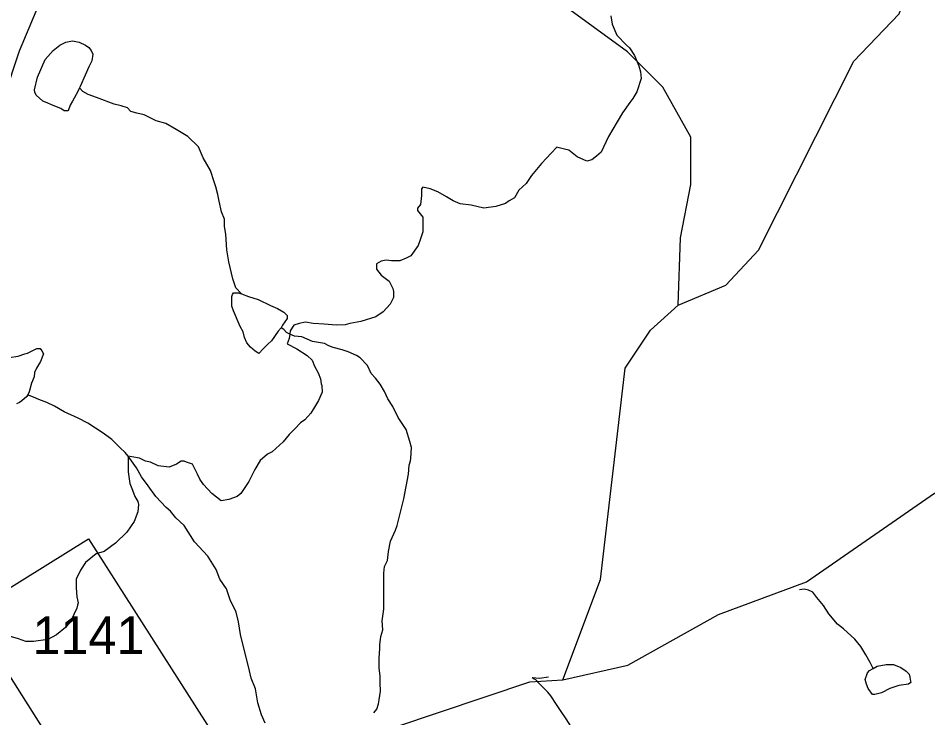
# Model space of a CAD drawing. Extents: x 2001466 to 2224147, y 644118 to 847247.
# Drawn here: x 2014651 to 2017667, y 716870 to 719190 of the extents above; entities that cross this region are included whole.
import ezdxf

# ---------------------------------------------------------------- set-up
doc = ezdxf.new("R2010")
doc.units = 0
for name, color, linetype in [('Exist Hydrographic Creek Single Shore', 7, 'Continuous'), ('Exist Hydrographic Misc Water Feature', 7, 'Continuous'), ('Exist Road Non-System Type 51', 7, 'Continuous'), ('Exist Road Secondary Type 51 Attributed', 7, 'Continuous'), ('Exist Road Secondary Type 51 Number Label', 7, 'Continuous')]:
    doc.layers.add(name, color=color, linetype=linetype)

msp = doc.modelspace()

# ---------------------------------------------------------------- linework, layer by layer
at = {"layer": 'Exist Hydrographic Creek Single Shore'}
for points in [[(2016457.2, 716996.2), (2016673.1, 717044.4), (2016973.1, 717212.1), (2017265.1, 717321), (2017690.1, 717614.3), (2018156, 717755.6), (2018439.2, 717930.3), (2018981.2, 718096.5)], [(2015574, 716610.6), (2015590, 716646.4), (2015749.1, 716787.6), (2016348.1, 716988.6), (2016457.2, 716996.2)]]:
    msp.add_lwpolyline(points, dxfattribs=at)
at = {"layer": 'Exist Hydrographic Misc Water Feature'}
for points in [[(2016672.1, 719078.7), (2016330.2, 719328.4), (2015864.2, 719554.5)], [(2016839.2, 718238.5), (2016997.1, 718304.3), (2017106.2, 718420.2), (2017422.1, 719047), (2017572.2, 719204.7), (2017614.1, 719321.9), (2017622.1, 719479.3), (2017588.2, 719502.9)], [(2016616.5, 719198), (2016620.6, 719170.1), (2016636.6, 719134.1), (2016668.6, 719100.1), (2016678.6, 719092.1), (2016694.6, 719066.2), (2016708.6, 719032.2), (2016714.7, 719012.2), (2016716.6, 718990.2), (2016702.6, 718946.2), (2016688.7, 718924.2), (2016678.8, 718910.2), (2016654.8, 718876.1), (2016636.8, 718846.2), (2016608.7, 718798.1), (2016584.7, 718746.1), (2016568.9, 718732.1), (2016552.9, 718720.1), (2016536.9, 718716.1), (2016504.9, 718730.1), (2016476.9, 718752), (2016462.9, 718756), (2016444.9, 718760), (2016436.9, 718762), (2016418.8, 718742.1), (2016402.8, 718726), (2016386.8, 718708), (2016352.8, 718668), (2016335, 718642), (2016311, 718620), (2016296.8, 718594), (2016279, 718584), (2016266.9, 718575.9), (2016235.1, 718565.9), (2016195.1, 718559.9), (2016153.1, 718569.9), (2016117, 718573.9), (2016093, 718583.9), (2016071.1, 718597.8), (2016043, 718613.8), (2016016.9, 718623.8), (2015992.9, 718629.8), (2015989, 718623.8), (2015989, 718601.8), (2015987, 718591.8), (2015984.9, 718571.8), (2015975.1, 718559.8), (2015975.1, 718551.8), (2015992.9, 718529.8), (2015992.9, 718511.8), (2015992.9, 718481.8), (2015984.9, 718457.8), (2015977.1, 718435.8), (2015953.2, 718401.8), (2015937.2, 718393.8), (2015917.1, 718385.8), (2015889.2, 718385.8), (2015871.1, 718387.7), (2015855.1, 718383.7), (2015839.1, 718375.7), (2015839.1, 718357.7), (2015855.1, 718337.7), (2015881.2, 718317.7), (2015893.1, 718293.8), (2015895.1, 718283.8), (2015895.1, 718263.8), (2015885.1, 718241.8), (2015861.3, 718215.7), (2015837.3, 718199.7), (2015787.3, 718183.7), (2015751.2, 718177.7), (2015735.2, 718173.6), (2015705.2, 718171.6), (2015665.3, 718175.6), (2015629.2, 718177.6), (2015603.3, 718181.6), (2015583.2, 718177.6), (2015565.2, 718171.6), (2015553.3, 718153.6), (2015551.3, 718141.6)], [(2014854.9, 718959.1), (2014848.9, 718947.1), (2014830.9, 718915), (2014822.9, 718901.1), (2014817, 718883), (2014803, 718883), (2014793, 718891), (2014761, 718903), (2014746.8, 718909), (2014732.9, 718915), (2014710.9, 718935), (2014706.8, 718945), (2014705, 718953), (2014714.8, 718994.9), (2014740.9, 719053), (2014766.9, 719083), (2014788.9, 719101), (2014809, 719111), (2014830.7, 719115), (2014852.8, 719111), (2014874.8, 719101), (2014884.8, 719093.1), (2014892.8, 719083.1), (2014899, 719071.1), (2014894.9, 719049.1), (2014884.8, 719029.1), (2014872.9, 719001.1), (2014856.9, 718963.1), (2014854.9, 718959.1)], [(2016839.2, 718238.5), (2016847.2, 718461.5), (2016881.2, 718638), (2016881.2, 718795.6), (2016789.1, 718961.4), (2016672.1, 719078.7)], [(2015391.3, 718275.5), (2015373.3, 718295.4), (2015363.2, 718325.5), (2015349.1, 718381.5), (2015343.1, 718421.4), (2015339.2, 718473.4), (2015335.1, 718499.4), (2015335.1, 718523.4), (2015325.1, 718547.4), (2015317.1, 718583.4), (2015313, 718605.4), (2015307, 718631.3), (2015301.1, 718647.4), (2015289, 718685.4), (2015265, 718727.3), (2015249, 718763.3), (2015213.1, 718797.4), (2015175, 718821.3), (2015140.9, 718841.2), (2015109, 718849.2), (2015069, 718869.2), (2015045, 718875.2), (2015024.9, 718881.1), (2015013, 718893.1), (2014992.9, 718899.2), (2014968.9, 718905.2), (2014910.9, 718927.1), (2014883, 718937.1), (2014864.9, 718947.1), (2014854.9, 718959.1)], [(2015523.2, 718163.6), (2015513.3, 718151.6), (2015491.4, 718119.5), (2015479.3, 718109.5), (2015463.3, 718093.5), (2015449.3, 718077.5), (2015437.4, 718085.5), (2015421.5, 718099.5), (2015409.4, 718113.5), (2015401.4, 718131.5), (2015397.3, 718149.5), (2015387.2, 718167.4), (2015365.3, 718219.5), (2015359.3, 718235.5), (2015359.3, 718251.5), (2015359.3, 718267.5), (2015361.2, 718273.5), (2015365.3, 718279.5), (2015381.3, 718279.5), (2015391.3, 718275.5)], [(2015391.3, 718275.5), (2015415.3, 718267.5), (2015447.3, 718257.5), (2015487.3, 718237.5), (2015511.3, 718227.5), (2015531.4, 718215.5), (2015537.3, 718209.5), (2015543.3, 718203.5), (2015543.3, 718193.6), (2015527.3, 718171.5), (2015523.2, 718163.6)], [(2016457.2, 716996.2), (2016582, 717328.4), (2016664.1, 718028.9), (2016748.1, 718155.1), (2016839.2, 718238.5)], [(2015551.3, 718141.6), (2015541.2, 718147.6), (2015531.4, 718157.6), (2015523.2, 718163.6)], [(2015551.3, 718141.6), (2015549.2, 718127.6), (2015543.5, 718109.6), (2015575.2, 718093.6), (2015609.3, 718071.6), (2015625.5, 718055.6), (2015633.5, 718035.6), (2015645.4, 718013.7), (2015653.4, 717993.7), (2015655.4, 717977.7), (2015657.5, 717971.7), (2015659.3, 717949.7), (2015647.4, 717921.6), (2015637.4, 717905.6), (2015621.6, 717879.7), (2015601.5, 717857.7), (2015587.5, 717847.7), (2015569.5, 717829.7), (2015549.4, 717809.6), (2015529.5, 717785.6), (2015493.4, 717751.6), (2015477.4, 717743.6), (2015453.4, 717723.6), (2015435.4, 717693.6), (2015415.7, 717653.5), (2015389.7, 717613.5), (2015377.6, 717603.6), (2015349.7, 717593.5), (2015323.6, 717589.5), (2015293.7, 717613.4), (2015265.6, 717643.5), (2015253.7, 717661.5), (2015245.7, 717677.5), (2015235.7, 717697.5), (2015229.5, 717711.5), (2015209.6, 717717.4), (2015201.6, 717721.4), (2015191.6, 717721.4), (2015175.6, 717711.4), (2015151.6, 717701.4), (2015115.7, 717705.4), (2015089.7, 717717.4), (2015073.7, 717721.4), (2015053.6, 717731.4), (2015027.5, 717735.3), (2015016, 717737.3)], [(2015829.9, 716885.9), (2015840, 716897.9), (2015845.9, 716915.9), (2015848, 716929.9), (2015852.1, 716957.9), (2015851.9, 716985.9), (2015851.9, 717007.9), (2015847.8, 717035.9), (2015847.8, 717067.9), (2015849.8, 717099.8), (2015849.8, 717111.8), (2015853.9, 717139.9), (2015859.9, 717161.9), (2015857.8, 717191.9), (2015863.8, 717229.8), (2015863.8, 717271.8), (2015863.8, 717321.9), (2015863.8, 717349.9), (2015865.8, 717371.8), (2015875.6, 717391.8), (2015879.5, 717421.8), (2015885.7, 717455.9), (2015901.7, 717491.8), (2015907.6, 717507.8), (2015929.6, 717595.9), (2015945.6, 717677.8), (2015947.4, 717707.9), (2015951.5, 717721.9), (2015953.6, 717729.9), (2015955.4, 717765.9), (2015949.5, 717785.8), (2015937.4, 717825.8), (2015911.3, 717865.9), (2015893.3, 717901.8), (2015877.3, 717927.8), (2015865.4, 717951.8), (2015851.4, 717975.8), (2015835.5, 717995.8), (2015821.3, 718011.7), (2015809.4, 718037.7), (2015785.4, 718063.7), (2015773.3, 718071.7), (2015745.2, 718083.7), (2015725.3, 718089.7), (2015695.2, 718097.7), (2015681.3, 718103.7), (2015667.3, 718111.7), (2015627.3, 718117.6), (2015591.2, 718133.6), (2015567.2, 718135.6), (2015551.3, 718141.6)], [(2014621.3, 718065), (2014651.5, 718069.1), (2014673.4, 718077.1), (2014681.4, 718079.1), (2014701.3, 718089.1), (2014713.4, 718095.1), (2014723.5, 718095.1), (2014729.4, 718087.1), (2014735.3, 718077.1), (2014725.3, 718051.1), (2014711.6, 718029.1), (2014705.4, 718015.1), (2014703.6, 718001.1), (2014695.6, 717979.1), (2014687.6, 717951.1), (2014683.5, 717941.1)], [(2014683.5, 717941.1), (2014679.6, 717935.1), (2014663.6, 717921.1), (2014655.6, 717915.1), (2014645.5, 717911.1)], [(2015016, 717737.3), (2015005.6, 717749.3), (2014989.4, 717765.3), (2014961.5, 717793.3), (2014933.4, 717813.3), (2014881.6, 717847.2), (2014849.6, 717863.2), (2014803.4, 717885.1), (2014771.4, 717903.1), (2014745.6, 717915.1), (2014719.6, 717925.1), (2014701.5, 717933.1), (2014687.6, 717939.1), (2014683.5, 717941.1)], [(2015016, 717737.3), (2015015.7, 717713.4), (2015015.7, 717685.3), (2015021.6, 717647.3), (2015029.6, 717625.3), (2015037.6, 717603.3), (2015047.6, 717587.4), (2015049.7, 717577.4), (2015047.6, 717553.3), (2015035.8, 717521.3), (2015011.8, 717485.3), (2014973.8, 717449.4), (2014935.7, 717421.3), (2014909.6, 717413.3), (2014873.8, 717385.3), (2014857.8, 717359.3), (2014843.8, 717329.2), (2014843.8, 717301.3), (2014845.9, 717271.3), (2014849.8, 717251.3), (2014847.9, 717243.3), (2014845.9, 717233.3), (2014826, 717191.2), (2014807.9, 717169.2), (2014778, 717145.2), (2014749.9, 717129.2), (2014701.9, 717123.2), (2014675.9, 717123.1), (2014651.9, 717131.2), (2014626.1, 717139.2)], [(2015470.1, 716851.6), (2015458, 716879.7), (2015446.1, 716919.7), (2015438.1, 716965.6), (2015423.9, 717001.7), (2015418, 717025.7), (2015409.8, 717061.6), (2015397.9, 717105.6), (2015387.8, 717145.6), (2015381.9, 717187.6), (2015373.9, 717219.6), (2015353.8, 717261.6), (2015341.7, 717297.5), (2015319.7, 717329.5), (2015307.6, 717361.5), (2015279.8, 717405.5), (2015235.7, 717453.5), (2015201.8, 717507.5), (2015173.8, 717533.5), (2015155.7, 717555.4), (2015141.6, 717567.4), (2015107.7, 717603.4), (2015081.7, 717639.3), (2015059.5, 717669.3), (2015043.5, 717699.3), (2015016, 717737.3)], [(2017485.7, 717032.9), (2017475.7, 717052.9), (2017461.5, 717078.8), (2017445.5, 717106.8), (2017425.6, 717130.8), (2017387.5, 717164.8), (2017367.6, 717180.8), (2017339.5, 717214.7), (2017321.7, 717242.8), (2017299.5, 717268.8), (2017285.6, 717286.7), (2017271.4, 717292.7), (2017257.7, 717296.7), (2017241.5, 717294.7)], [(2017485.7, 717032.9), (2017499.7, 717040.9), (2017529.8, 717046.9), (2017553.6, 717046.9), (2017577.6, 717036.9), (2017595.6, 717024.9), (2017605.7, 717014.9), (2017607.7, 717005), (2017609.8, 716991), (2017611.6, 716987), (2017603.6, 716980.9), (2017571.6, 716976.9), (2017541.7, 716966.9), (2017513.8, 716952.9), (2017491.7, 716946.9), (2017483.7, 716946.9), (2017469.7, 716966.9), (2017463.8, 716980.9), (2017459.7, 716996.9), (2017467.7, 717018.9), (2017473.6, 717026.9), (2017485.7, 717032.9)], [(2016409.8, 717004.2), (2016379.9, 717000.2), (2016355.9, 717002.2)], [(2016728, 716658.4), (2016684, 716676.4), (2016644, 716696.4), (2016620, 716708.3), (2016609.9, 716718.3), (2016575.9, 716742.3), (2016538, 716772.4), (2016522, 716794.3), (2016501.9, 716818.3), (2016483.8, 716842.3), (2016467.8, 716866.3), (2016451.8, 716890.3), (2016435.8, 716914.2), (2016417.8, 716942.2), (2016407.8, 716954.3), (2016389.9, 716972.2), (2016377.8, 716984.2), (2016367.8, 716996.2), (2016361.8, 716998.2), (2016355.9, 717002.2)]]:
    msp.add_lwpolyline(points, dxfattribs=at)
at = {"layer": 'Exist Road Non-System Type 51'}
msp.add_lwpolyline([(2014519.1, 717236.5), (2014884.6, 717463.4), (2015335.7, 716756.6)], dxfattribs=at)
at = {"layer": 'Exist Road Secondary Type 51 Attributed'}
for points in [[(2014384.5, 717906.4), (2014396.5, 718158.6), (2014428.4, 718380.5), (2014552, 718771.7), (2014655.7, 719081.4), (2014820.8, 719477.3), (2014902.2, 719648.2), (2015001.1, 719815.8), (2015215.7, 720181.4), (2015372.1, 720420.9), (2015484.5, 720588.5), (2015522.8, 720673.1), (2015553.1, 720784.9), (2015589, 721048.3), (2015595, 721117.8), (2015622.9, 721186.4)], [(2015100.2, 716248.8), (2014864.7, 716627.5), (2014623, 717009.1), (2014503.4, 717270.9), (2014432.4, 717521.6), (2014394.1, 717778.6), (2014384.5, 717906.4)]]:
    msp.add_lwpolyline(points, dxfattribs=at)

# ---------------------------------------------------------------- texts
at = {"layer": 'Exist Road Secondary Type 51 Number Label'}
msp.add_text('1141', height=125, dxfattribs=at).set_placement((2014698, 717081))

doc.saveas('drawing.dxf')
